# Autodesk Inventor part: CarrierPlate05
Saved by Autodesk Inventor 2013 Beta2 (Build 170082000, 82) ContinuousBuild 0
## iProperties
Created: 2008-02
Part Number: CarrierPlate05
Document SubType Name: Modeling
Designer: grh
Density: 1 g/cm^3
Material: Generic
Author: grh
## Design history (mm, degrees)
sketch "Sketch1"
  geometry: L1 (48.514, 0)-(0, 0); L2 (0, 0)-(37.164, 31.184); L3 (8.424, 47.777)-(0, 0); L4 (-24.257, 42.014)-(0, 0); L5 (-45.588, 16.593)-(0, 0); C1 r 53.34 at (0, 0)
  constraints: 10 end point, 4 equal length, 1 centre point, 1 horizontal, 1 other
  dimensions: "BlankDiameter" = 106.68 diameter of C1; "PlanetRadius" = 48.514 distance of L1.start L1.end; "Angle1" = 40 deg angle of L2 L1; "Angle2" = 40 deg angle of L3 L2; "Angle3" = 40 deg angle of L4 L3; "Angle4" = 40 deg angle of L5 L4
extrude "Extrusion1" new body sketch "Sketch1" stored distance "d9" = 13.97; taper "d10" = 0 deg
node "Axis1"
node "Axis2"
node "Axis3"
node "Axis4"
node "Axis5"
node "Axis6"
body "Solid1"
